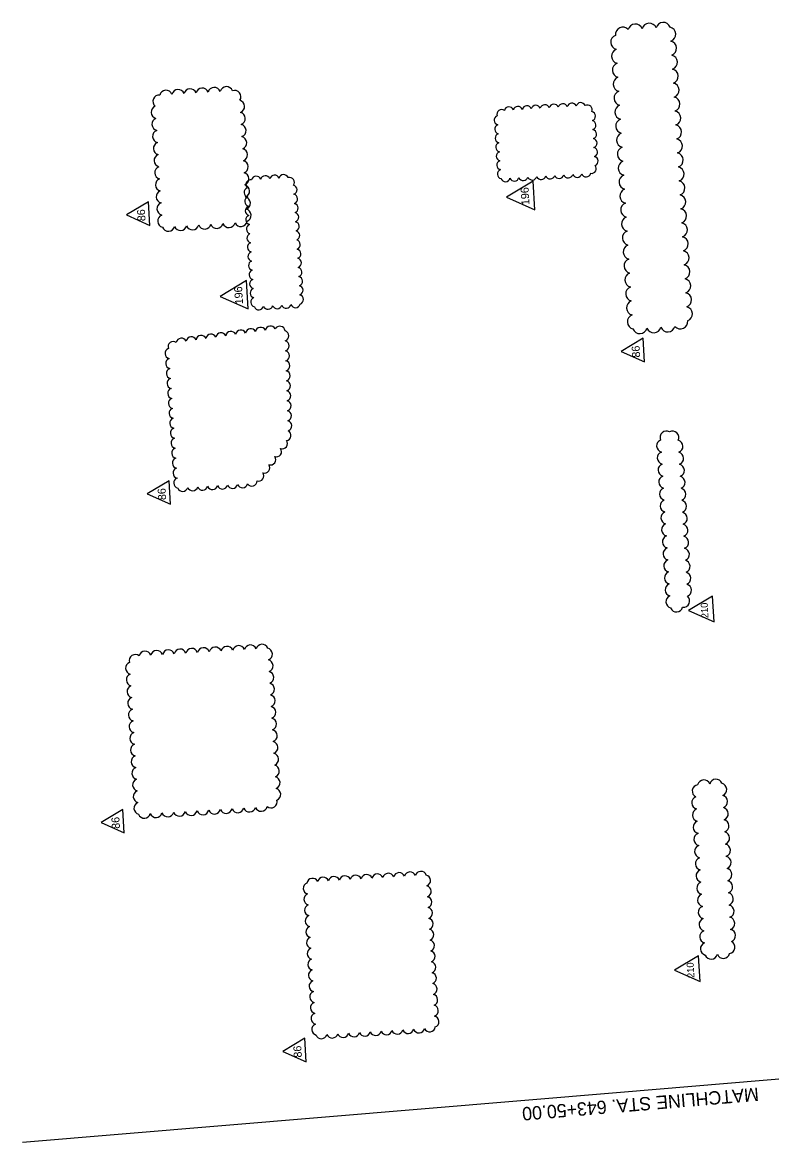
# Model space of a CAD drawing. Extents: x 928602 to 929490, y 640080 to 641338.
# Drawn here: x 928667 to 929117, y 640162 to 640834 of the extents above; entities that cross this region are included whole.
import ezdxf

# ---------------------------------------------------------------- set-up
doc = ezdxf.new("R2010")
doc.units = 0
doc.layers.add('NonPlottingEle_dp', color=7, linetype='Continuous')
doc.layers.add('ScratchEle_dp', color=7, linetype='Continuous')

msp = doc.modelspace()

# ---------------------------------------------------------------- linework, layer by layer
at = {"layer": 'NonPlottingEle_dp'}
for points in [[(928957.78, 640729.4), (928974.67, 640721.87), (928973.66, 640738.89)], [(928729.91, 640718.69), (928743.87, 640712.47), (928743.03, 640726.53)], [(928786, 640669.89), (928802.89, 640662.36), (928801.87, 640679.38)], [(929026.58, 640636.89), (929040.53, 640630.67), (929039.7, 640644.73)], [(928742.28, 640551.42), (928756.24, 640545.2), (928755.4, 640559.26)], [(929066.88, 640481.48), (929082.24, 640474.64), (929081.31, 640490.1)], [(928714.58, 640354.29), (928728.54, 640348.06), (928727.7, 640362.12)], [(929058.46, 640265.72), (929073.81, 640258.88), (929072.89, 640274.34)], [(928823.68, 640217.07), (928837.64, 640210.85), (928836.8, 640224.9)]]:
    msp.add_lwpolyline(points, close=True, dxfattribs=at)
for centre, radius, start, end in [((929035.02, 640828.79), 4.4, 20.91308, 165.91308), ((929043.41, 640829.29), 4.4, 20.91308, 165.91308), ((929051.79, 640829.79), 4.4, 20.91308, 165.91308), ((929024.66, 640822.31), 4.4, 110.91308, 255.91308), ((929027.46, 640826.94), 4.4, 41.64404, 186.64404), ((929054.83, 640827.09), 4.4, 290.91308, 75.91308), ((929055.33, 640818.7), 4.4, 290.91308, 75.91308), ((929025.16, 640813.93), 4.4, 110.91308, 255.91308), ((929055.83, 640810.32), 4.4, 290.91308, 75.91308), ((929025.66, 640805.54), 4.4, 110.91308, 255.91308), ((929056.33, 640801.93), 4.4, 290.91308, 75.91308), ((929026.16, 640797.16), 4.4, 110.91308, 255.91308), ((928753.55, 640789.69), 3.81, 20.91308, 165.91308), ((928760.8, 640790.12), 3.81, 20.91308, 165.91308), ((928768.05, 640790.55), 3.81, 20.91308, 165.91308), ((928775.3, 640790.98), 3.81, 20.91308, 165.91308), ((928782.55, 640791.42), 3.81, 20.91308, 165.91308), ((928789.8, 640791.85), 3.81, 20.91308, 165.91308), ((928794.68, 640789.64), 3.81, 325.30711, 110.30711), ((929026.66, 640788.77), 4.4, 110.91308, 255.91308), ((929056.83, 640793.55), 4.4, 290.91308, 75.91308), ((928749.54, 640786.82), 3.81, 85.27111, 230.27111), ((928796.88, 640783.77), 3.81, 290.91308, 75.91308), ((928996.9, 640782.93), 2.83, 20.91308, 165.91308), ((929002.28, 640783.25), 2.83, 20.91308, 165.91308), ((929057.33, 640785.17), 4.4, 290.91308, 75.91308), ((928748.47, 640780.34), 3.81, 110.91308, 255.91308), ((928797.31, 640776.52), 3.81, 290.91308, 75.91308), ((928954.85, 640779.08), 2.82, 54.19116, 199.19116), ((928959.24, 640780.68), 2.83, 20.91308, 165.91308), ((928964.62, 640781), 2.83, 20.91308, 165.91308), ((928970, 640781.33), 2.83, 20.91308, 165.91308), ((928975.38, 640781.65), 2.83, 20.91308, 165.91308), ((928980.76, 640781.97), 2.83, 20.91308, 165.91308), ((928986.14, 640782.29), 2.83, 20.91308, 165.91308), ((928991.52, 640782.61), 2.83, 20.91308, 165.91308), ((929006.37, 640781.83), 2.83, 335.79322, 120.79322), ((929008.26, 640777.93), 2.83, 290.91308, 75.91308), ((929027.16, 640780.39), 4.4, 110.91308, 255.91308), ((929057.83, 640776.78), 4.4, 290.91308, 75.91308), ((928748.9, 640773.09), 3.81, 110.91308, 255.91308), ((928797.75, 640769.27), 3.81, 290.91308, 75.91308), ((928953.19, 640775.51), 2.83, 110.91308, 255.91308), ((928953.51, 640770.13), 2.83, 110.91308, 255.91308), ((929008.58, 640772.55), 2.83, 290.91308, 75.91308), ((929027.66, 640772), 4.4, 110.91308, 255.91308), ((929058.33, 640768.4), 4.4, 290.91308, 75.91308), ((928749.33, 640765.84), 3.81, 110.91308, 255.91308), ((928798.18, 640762.02), 3.81, 290.91308, 75.91308), ((928953.83, 640764.75), 2.83, 110.91308, 255.91308), ((929008.9, 640767.17), 2.83, 290.91308, 75.91308), ((929028.16, 640763.62), 4.4, 110.91308, 255.91308), ((928749.76, 640758.59), 3.81, 110.91308, 255.91308), ((928954.15, 640759.37), 2.83, 110.91308, 255.91308), ((929009.22, 640761.79), 2.83, 290.91308, 75.91308), ((929009.54, 640756.41), 2.83, 290.91308, 75.91308), ((929028.66, 640755.24), 4.4, 110.91308, 255.91308), ((929058.83, 640760.01), 4.4, 290.91308, 75.91308), ((928750.2, 640751.34), 3.81, 110.91308, 255.91308), ((928798.61, 640754.77), 3.81, 290.91308, 75.91308), ((928954.47, 640753.99), 2.83, 110.91308, 255.91308), ((929009.86, 640751.03), 2.83, 290.91308, 75.91308), ((929059.33, 640751.63), 4.4, 290.91308, 75.91308), ((928750.63, 640744.09), 3.81, 110.91308, 255.91308), ((928799.04, 640747.52), 3.81, 290.91308, 75.91308), ((928954.79, 640748.61), 2.83, 110.91308, 255.91308), ((928955.11, 640743.23), 2.83, 110.91308, 255.91308), ((929008.81, 640746.46), 2.82, 258.12844, 43.12844), ((929029.16, 640746.85), 4.4, 110.91308, 255.91308), ((929059.83, 640743.24), 4.4, 290.91308, 75.91308), ((928751.06, 640736.84), 3.81, 110.91308, 255.91308), ((928799.48, 640740.27), 3.81, 290.91308, 75.91308), ((928804.34, 640736.94), 2.88, 79.35481, 224.35481), ((928807.67, 640739.07), 2.88, 20.91308, 165.91308), ((928813.15, 640739.39), 2.88, 20.91308, 165.91308), ((928818.63, 640739.72), 2.88, 20.91308, 165.91308), ((928824.12, 640740.05), 2.88, 20.91308, 165.91308), ((928827.67, 640738.33), 2.88, 322.50076, 107.50076), ((928957.07, 640741.5), 2.83, 200.91308, 345.91308), ((928962.45, 640741.82), 2.83, 200.91308, 345.91308), ((928967.83, 640742.14), 2.83, 200.91308, 345.91308), ((928973.21, 640742.46), 2.83, 200.91308, 345.91308), ((928978.59, 640742.78), 2.83, 200.91308, 345.91308), ((928983.97, 640743.11), 2.83, 200.91308, 345.91308), ((928989.35, 640743.43), 2.83, 200.91308, 345.91308), ((928994.73, 640743.75), 2.83, 200.91308, 345.91308), ((929000.11, 640744.07), 2.83, 200.91308, 345.91308), ((929005.49, 640744.39), 2.83, 200.91308, 345.91308), ((929029.66, 640738.47), 4.4, 110.91308, 255.91308), ((929060.33, 640734.86), 4.4, 290.91308, 75.91308), ((928751.49, 640729.59), 3.81, 110.91308, 255.91308), ((928803.31, 640732.24), 2.88, 110.91308, 255.91308), ((928799.91, 640733.02), 3.81, 290.91308, 75.91308), ((928829.26, 640733.78), 2.88, 290.91308, 75.91308), ((929030.16, 640730.08), 4.4, 110.91308, 255.91308), ((928751.93, 640722.34), 3.81, 110.91308, 255.91308), ((928803.64, 640726.75), 2.88, 110.91308, 255.91308), ((928800.34, 640725.77), 3.81, 290.91308, 75.91308), ((928829.58, 640728.3), 2.88, 290.91308, 75.91308), ((928829.91, 640722.81), 2.88, 290.91308, 75.91308), ((929030.66, 640721.7), 4.4, 110.91308, 255.91308), ((929060.83, 640726.47), 4.4, 290.91308, 75.91308), ((928752.36, 640715.08), 3.81, 110.91308, 255.91308), ((928803.97, 640721.27), 2.88, 110.91308, 255.91308), ((928800.77, 640718.52), 3.81, 290.91308, 75.91308), ((928830.24, 640717.33), 2.88, 290.91308, 75.91308), ((929061.33, 640718.09), 4.4, 290.91308, 75.91308), ((928754.99, 640712.75), 3.81, 200.91308, 345.91308), ((928762.24, 640713.18), 3.81, 200.91308, 345.91308), ((928769.49, 640713.62), 3.81, 200.91308, 345.91308), ((928776.74, 640714.05), 3.81, 200.91308, 345.91308), ((928783.99, 640714.48), 3.81, 200.91308, 345.91308), ((928791.24, 640714.91), 3.81, 200.91308, 345.91308), ((928798.38, 640715.61), 3.81, 205.22298, 350.22298), ((928804.29, 640715.79), 2.88, 110.91308, 255.91308), ((928804.62, 640710.3), 2.88, 110.91308, 255.91308), ((928830.56, 640711.85), 2.88, 290.91308, 75.91308), ((929031.16, 640713.31), 4.4, 110.91308, 255.91308), ((929061.83, 640709.7), 4.4, 290.91308, 75.91308), ((928804.95, 640704.82), 2.88, 110.91308, 255.91308), ((928830.89, 640706.37), 2.88, 290.91308, 75.91308), ((929031.66, 640704.93), 4.4, 110.91308, 255.91308), ((929062.33, 640701.32), 4.4, 290.91308, 75.91308), ((928805.27, 640699.34), 2.88, 110.91308, 255.91308), ((928831.22, 640700.88), 2.88, 290.91308, 75.91308), ((929032.16, 640696.54), 4.4, 110.91308, 255.91308), ((928805.6, 640693.85), 2.88, 110.91308, 255.91308), ((928831.55, 640695.4), 2.88, 290.91308, 75.91308), ((928831.87, 640689.92), 2.88, 290.91308, 75.91308), ((929032.66, 640688.16), 4.4, 110.91308, 255.91308), ((929062.83, 640692.93), 4.4, 290.91308, 75.91308), ((928805.93, 640688.37), 2.88, 110.91308, 255.91308), ((928806.25, 640682.89), 2.88, 110.91308, 255.91308), ((928832.2, 640684.43), 2.88, 290.91308, 75.91308), ((929063.33, 640684.55), 4.4, 290.91308, 75.91308), ((928806.58, 640677.4), 2.88, 110.91308, 255.91308), ((928832.53, 640678.95), 2.88, 290.91308, 75.91308), ((929033.16, 640679.77), 4.4, 110.91308, 255.91308), ((929063.83, 640676.16), 4.4, 290.91308, 75.91308), ((928806.91, 640671.92), 2.88, 110.91308, 255.91308), ((928832.85, 640673.47), 2.88, 290.91308, 75.91308), ((929033.67, 640671.39), 4.4, 110.91308, 255.91308), ((929064.33, 640667.78), 4.4, 290.91308, 75.91308), ((928807.24, 640666.44), 2.88, 110.91308, 255.91308), ((928825.67, 640665.65), 2.88, 200.91308, 345.91308), ((928831.16, 640665.98), 2.88, 200.91308, 345.91308), ((928833.05, 640668.02), 2.88, 288.19279, 73.19279), ((929034.17, 640663), 4.4, 110.91308, 255.91308), ((928809.22, 640664.67), 2.88, 200.91308, 345.91308), ((928814.71, 640665), 2.88, 200.91308, 345.91308), ((928820.19, 640665.33), 2.88, 200.91308, 345.91308), ((929034.67, 640654.62), 4.4, 110.91308, 255.91308), ((929064.83, 640659.39), 4.4, 290.91308, 75.91308), ((928816.22, 640649), 3.14, 25.29706, 170.29706), ((928821.8, 640648.83), 3.14, 6.17334, 151.17334), ((929046.09, 640652.42), 4.4, 200.91308, 345.91308), ((929054.48, 640652.92), 4.4, 200.91308, 345.91308), ((929062.04, 640654.77), 4.4, 221.64404, 6.64404), ((928762.83, 640641.69), 3.14, 25.29706, 170.29706), ((928768.77, 640642.5), 3.14, 25.29706, 170.29706), ((928774.7, 640643.32), 3.14, 25.29706, 170.29706), ((928780.63, 640644.13), 3.14, 25.29706, 170.29706), ((928786.56, 640644.94), 3.14, 25.29706, 170.29706), ((928792.49, 640645.75), 3.14, 25.29706, 170.29706), ((928798.42, 640646.56), 3.14, 25.29706, 170.29706), ((928804.35, 640647.38), 3.14, 25.29706, 170.29706), ((928810.29, 640648.19), 3.14, 25.29706, 170.29706), ((928824.07, 640646.15), 3.14, 289.35004, 74.35004), ((929037.71, 640651.92), 4.4, 200.91308, 345.91308), ((928756.14, 640635.64), 3.14, 111.32861, 256.32861), ((928757.95, 640639.65), 3.14, 55.12604, 200.12604), ((928824.27, 640640.16), 3.14, 289.35004, 74.35004), ((928756.54, 640629.67), 3.14, 111.32861, 256.32861), ((928824.46, 640634.18), 3.14, 289.35004, 74.35004), ((928824.65, 640628.19), 3.14, 289.35004, 74.35004), ((928756.94, 640623.7), 3.14, 111.32861, 256.32861), ((928824.85, 640622.21), 3.14, 289.35004, 74.35004), ((928757.34, 640617.72), 3.14, 111.32861, 256.32861), ((928825.04, 640616.23), 3.14, 289.35004, 74.35004), ((928757.74, 640611.75), 3.14, 111.32861, 256.32861), ((928825.23, 640610.24), 3.14, 289.35004, 74.35004), ((928758.14, 640605.78), 3.14, 111.32861, 256.32861), ((928825.43, 640604.26), 3.14, 289.35004, 74.35004), ((928758.54, 640599.8), 3.14, 111.32861, 256.32861), ((928825.62, 640598.28), 3.14, 289.35004, 74.35004), ((928758.94, 640593.83), 3.14, 111.32861, 256.32861), ((928825.81, 640592.29), 3.14, 289.35004, 74.35004), ((928759.34, 640587.86), 3.14, 111.32861, 256.32861), ((928759.74, 640581.88), 3.14, 111.32861, 256.32861), ((928825.39, 640586.55), 3.14, 277.25725, 62.25725), ((929053.63, 640585.3), 3.78, 59.80785, 204.80785), ((929057.33, 640585.25), 3.78, 333.47758, 118.47758), ((928760.14, 640575.91), 3.14, 111.32861, 256.32861), ((928819.73, 640576.75), 3.14, 251.34038, 36.34038), ((928823.26, 640581.58), 3.14, 251.34038, 36.34038), ((929051.55, 640580.19), 3.78, 110.91308, 255.91308), ((929059.8, 640579.89), 3.78, 290.91308, 75.91308), ((928760.54, 640569.94), 3.14, 111.32861, 256.32861), ((928816.2, 640571.91), 3.14, 251.34038, 36.34038), ((929051.98, 640573), 3.78, 110.91308, 255.91308), ((929060.23, 640572.7), 3.78, 290.91308, 75.91308), ((928760.94, 640563.96), 3.14, 111.32861, 256.32861), ((928809.13, 640562.25), 3.14, 251.34038, 36.34038), ((928812.66, 640567.08), 3.14, 251.34038, 36.34038), ((929052.41, 640565.8), 3.78, 110.91308, 255.91308), ((929060.66, 640565.51), 3.78, 290.91308, 75.91308), ((928761.34, 640557.99), 3.14, 111.32861, 256.32861), ((928799.39, 640558.2), 3.14, 200.91308, 345.91308), ((928804.99, 640559.25), 3.14, 215.3842, 0.3842), ((929052.84, 640558.61), 3.78, 110.91308, 255.91308), ((929061.08, 640558.31), 3.78, 290.91308, 75.91308), ((928763.53, 640556.06), 3.14, 200.91308, 345.91308), ((928769.5, 640556.42), 3.14, 200.91308, 345.91308), ((928775.48, 640556.77), 3.14, 200.91308, 345.91308), ((928781.46, 640557.13), 3.14, 200.91308, 345.91308), ((928787.43, 640557.48), 3.14, 200.91308, 345.91308), ((928793.41, 640557.84), 3.14, 200.91308, 345.91308), ((929053.27, 640551.42), 3.78, 110.91308, 255.91308), ((929061.51, 640551.12), 3.78, 290.91308, 75.91308), ((929053.7, 640544.22), 3.78, 110.91308, 255.91308), ((929061.94, 640543.93), 3.78, 290.91308, 75.91308), ((929054.13, 640537.03), 3.78, 110.91308, 255.91308), ((929062.37, 640536.73), 3.78, 290.91308, 75.91308), ((929054.56, 640529.84), 3.78, 110.91308, 255.91308), ((929062.8, 640529.54), 3.78, 290.91308, 75.91308), ((929054.99, 640522.64), 3.78, 110.91308, 255.91308), ((929063.23, 640522.35), 3.78, 290.91308, 75.91308), ((929055.42, 640515.45), 3.78, 110.91308, 255.91308), ((929063.66, 640515.15), 3.78, 290.91308, 75.91308), ((929055.84, 640508.26), 3.78, 110.91308, 255.91308), ((929064.09, 640507.96), 3.78, 290.91308, 75.91308), ((929056.27, 640501.06), 3.78, 110.91308, 255.91308), ((929064.52, 640500.76), 3.78, 290.91308, 75.91308), ((929056.7, 640493.87), 3.78, 110.91308, 255.91308), ((929064.95, 640493.57), 3.78, 290.91308, 75.91308), ((929057.13, 640486.68), 3.78, 110.91308, 255.91308), ((929059.74, 640484.36), 3.78, 200.91308, 345.91308), ((929063.81, 640487.2), 3.78, 263.87088, 48.87088), ((928741.06, 640453.38), 3.68, 20.91308, 165.91308), ((928748.06, 640453.8), 3.68, 20.91308, 165.91308), ((928755.07, 640454.22), 3.68, 20.91308, 165.91308), ((928762.07, 640454.64), 3.68, 20.91308, 165.91308), ((928769.08, 640455.05), 3.68, 20.91308, 165.91308), ((928776.08, 640455.47), 3.68, 20.91308, 165.91308), ((928783.09, 640455.89), 3.68, 20.91308, 165.91308), ((928790.09, 640456.31), 3.68, 20.91308, 165.91308), ((928797.1, 640456.72), 3.68, 20.91308, 165.91308), ((928804.1, 640457.14), 3.68, 20.91308, 165.91308), ((928811.11, 640457.56), 3.68, 20.91308, 165.91308), ((928813.65, 640455.3), 3.68, 290.91308, 75.91308), ((928733.02, 640446.88), 3.68, 110.91308, 255.91308), ((928735.22, 640451.38), 3.68, 51.9161, 196.9161), ((928814.07, 640448.3), 3.68, 290.91308, 75.91308), ((928733.44, 640439.87), 3.68, 110.91308, 255.91308), ((928814.49, 640441.29), 3.68, 290.91308, 75.91308), ((928814.9, 640434.29), 3.68, 290.91308, 75.91308), ((928733.86, 640432.87), 3.68, 110.91308, 255.91308), ((928815.32, 640427.28), 3.68, 290.91308, 75.91308), ((928734.27, 640425.86), 3.68, 110.91308, 255.91308), ((928815.74, 640420.28), 3.68, 290.91308, 75.91308), ((928734.69, 640418.86), 3.68, 110.91308, 255.91308), ((928816.16, 640413.27), 3.68, 290.91308, 75.91308), ((928735.11, 640411.85), 3.68, 110.91308, 255.91308), ((928816.58, 640406.27), 3.68, 290.91308, 75.91308), ((928735.53, 640404.85), 3.68, 110.91308, 255.91308), ((928816.99, 640399.26), 3.68, 290.91308, 75.91308), ((928735.94, 640397.84), 3.68, 110.91308, 255.91308), ((928736.36, 640390.84), 3.68, 110.91308, 255.91308), ((928817.41, 640392.26), 3.68, 290.91308, 75.91308), ((928736.78, 640383.83), 3.68, 110.91308, 255.91308), ((928817.83, 640385.25), 3.68, 290.91308, 75.91308), ((928737.2, 640376.83), 3.68, 110.91308, 255.91308), ((928818.25, 640378.25), 3.68, 290.91308, 75.91308), ((929072.98, 640373.19), 3.83, 99.20788, 244.20788), ((929076.08, 640376.04), 3.83, 20.91308, 165.91308), ((929083.38, 640376.47), 3.83, 20.91308, 165.91308), ((929086.03, 640374.12), 3.83, 290.91308, 75.91308), ((928737.62, 640369.82), 3.68, 110.91308, 255.91308), ((928818.66, 640371.24), 3.68, 290.91308, 75.91308), ((929072.68, 640366.16), 3.83, 110.91308, 255.91308), ((929086.47, 640366.82), 3.83, 290.91308, 75.91308), ((928738.03, 640362.82), 3.68, 110.91308, 255.91308), ((928789.61, 640363.49), 3.68, 200.91308, 345.91308), ((928796.61, 640363.9), 3.68, 200.91308, 345.91308), ((928803.62, 640364.32), 3.68, 200.91308, 345.91308), ((928810.62, 640364.74), 3.68, 200.91308, 345.91308), ((928816.46, 640366.74), 3.68, 231.9161, 16.9161), ((929086.9, 640359.53), 3.83, 290.91308, 75.91308), ((928740.57, 640360.56), 3.68, 200.91308, 345.91308), ((928747.58, 640360.98), 3.68, 200.91308, 345.91308), ((928754.58, 640361.4), 3.68, 200.91308, 345.91308), ((928761.59, 640361.81), 3.68, 200.91308, 345.91308), ((928768.59, 640362.23), 3.68, 200.91308, 345.91308), ((928775.6, 640362.65), 3.68, 200.91308, 345.91308), ((928782.6, 640363.07), 3.68, 200.91308, 345.91308), ((929073.12, 640358.86), 3.83, 110.91308, 255.91308), ((929087.34, 640352.23), 3.83, 290.91308, 75.91308), ((929073.55, 640351.56), 3.83, 110.91308, 255.91308), ((929073.99, 640344.26), 3.83, 110.91308, 255.91308), ((929087.77, 640344.93), 3.83, 290.91308, 75.91308), ((929074.42, 640336.96), 3.83, 110.91308, 255.91308), ((929088.21, 640337.63), 3.83, 290.91308, 75.91308), ((929074.86, 640329.66), 3.83, 110.91308, 255.91308), ((929088.64, 640330.33), 3.83, 290.91308, 75.91308), ((928860.86, 640318.91), 3.42, 20.91308, 165.91308), ((928867.37, 640319.3), 3.42, 20.91308, 165.91308), ((928873.88, 640319.69), 3.42, 20.91308, 165.91308), ((928880.39, 640320.08), 3.42, 20.91308, 165.91308), ((928886.9, 640320.46), 3.42, 20.91308, 165.91308), ((928893.41, 640320.85), 3.42, 20.91308, 165.91308), ((928899.92, 640321.24), 3.42, 20.91308, 165.91308), ((928906.43, 640321.63), 3.42, 20.91308, 165.91308), ((928908.79, 640319.53), 3.42, 290.91308, 75.91308), ((929075.29, 640322.36), 3.83, 110.91308, 255.91308), ((929089.08, 640323.03), 3.83, 290.91308, 75.91308), ((928839.3, 640314.81), 3.42, 110.91308, 255.91308), ((928841.45, 640317.47), 3.42, 26.00859, 171.00859), ((928847.84, 640318.13), 3.42, 20.91308, 165.91308), ((928854.35, 640318.52), 3.42, 20.91308, 165.91308), ((928909.18, 640313.02), 3.42, 290.91308, 75.91308), ((929075.73, 640315.06), 3.83, 110.91308, 255.91308), ((929089.51, 640315.73), 3.83, 290.91308, 75.91308), ((928839.69, 640308.3), 3.42, 110.91308, 255.91308), ((928909.57, 640306.51), 3.42, 290.91308, 75.91308), ((929076.16, 640307.76), 3.83, 110.91308, 255.91308), ((929089.95, 640308.43), 3.83, 290.91308, 75.91308), ((928840.08, 640301.79), 3.42, 110.91308, 255.91308), ((928909.95, 640300), 3.42, 290.91308, 75.91308), ((929076.6, 640300.46), 3.83, 110.91308, 255.91308), ((929090.38, 640301.13), 3.83, 290.91308, 75.91308), ((928840.46, 640295.28), 3.42, 110.91308, 255.91308), ((928910.34, 640293.49), 3.42, 290.91308, 75.91308), ((929077.03, 640293.16), 3.83, 110.91308, 255.91308), ((929090.82, 640293.83), 3.83, 290.91308, 75.91308), ((928840.85, 640288.77), 3.42, 110.91308, 255.91308), ((928910.73, 640286.98), 3.42, 290.91308, 75.91308), ((929077.47, 640285.87), 3.83, 110.91308, 255.91308), ((929091.26, 640286.53), 3.83, 290.91308, 75.91308), ((928841.24, 640282.26), 3.42, 110.91308, 255.91308), ((928911.12, 640280.47), 3.42, 290.91308, 75.91308), ((929077.9, 640278.57), 3.83, 110.91308, 255.91308), ((929090.96, 640279.5), 3.83, 279.20788, 64.20788), ((928841.63, 640275.75), 3.42, 110.91308, 255.91308), ((928911.51, 640273.96), 3.42, 290.91308, 75.91308), ((929080.55, 640276.22), 3.83, 200.91308, 345.91308), ((929087.85, 640276.65), 3.83, 200.91308, 345.91308), ((928842.02, 640269.24), 3.42, 110.91308, 255.91308), ((928911.9, 640267.45), 3.42, 290.91308, 75.91308), ((928842.41, 640262.73), 3.42, 110.91308, 255.91308), ((928912.28, 640260.94), 3.42, 290.91308, 75.91308), ((928842.79, 640256.22), 3.42, 110.91308, 255.91308), ((928912.67, 640254.43), 3.42, 290.91308, 75.91308), ((928843.18, 640249.71), 3.42, 110.91308, 255.91308), ((928913.06, 640247.92), 3.42, 290.91308, 75.91308), ((928843.57, 640243.2), 3.42, 110.91308, 255.91308), ((928913.45, 640241.42), 3.42, 290.91308, 75.91308), ((928843.96, 640236.69), 3.42, 110.91308, 255.91308), ((928913.84, 640234.91), 3.42, 290.91308, 75.91308), ((928844.35, 640230.18), 3.42, 110.91308, 255.91308), ((928866.24, 640229.25), 3.42, 200.91308, 345.91308), ((928872.75, 640229.64), 3.42, 200.91308, 345.91308), ((928879.26, 640230.03), 3.42, 200.91308, 345.91308), ((928885.77, 640230.41), 3.42, 200.91308, 345.91308), ((928892.28, 640230.8), 3.42, 200.91308, 345.91308), ((928898.79, 640231.19), 3.42, 200.91308, 345.91308), ((928905.3, 640231.58), 3.42, 200.91308, 345.91308), ((928911.68, 640232.25), 3.42, 206.00859, 351.00859), ((928846.71, 640228.09), 3.42, 200.91308, 345.91308), ((928853.22, 640228.47), 3.42, 200.91308, 345.91308), ((928859.73, 640228.86), 3.42, 200.91308, 345.91308)]:
    msp.add_arc(centre, radius, start, end, dxfattribs=at)
at = {"layer": 'ScratchEle_dp'}
msp.add_lwpolyline([(929384.91, 640222.63), (929026.17, 640192.5), (928667.43, 640162.36)], dxfattribs=at)

# ---------------------------------------------------------------- texts
at = {"layer": 'NonPlottingEle_dp'}
for s, height, p in [('196', 4.8, (928971.58, 640724.78)), ('86', 4.8, (928741.3, 640715.1)), ('196', 4.8, (928799.79, 640665.27)), ('86', 4.8, (929037.96, 640633.3)), ('86', 4.8, (928753.67, 640547.83)), ('210', 4.18, (929078.89, 640476.99)), ('86', 4.8, (928725.96, 640350.69)), ('210', 4.18, (929070.47, 640261.23)), ('86', 4.8, (928835.06, 640213.48))]:
    msp.add_text(s, height=height, rotation=93.41308, dxfattribs=at).set_placement(p)
at = {"layer": 'ScratchEle_dp'}
msp.add_text('MATCHLINE STA. 643+50.00', height=8, rotation=184.80152, dxfattribs=at).set_placement((929108.72, 640195.42))

doc.saveas('drawing.dxf')
